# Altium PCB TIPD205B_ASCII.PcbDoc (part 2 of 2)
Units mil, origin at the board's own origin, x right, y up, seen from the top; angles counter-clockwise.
Board outline 684.25 x 4724.41 mil, 4 copper layers (Top Layer, Signal Layer 1, Signal Layer 2, Bottom Layer), stack 61.6 mil thick; 36 components, 24 nets, 156 pads, 59 vias.
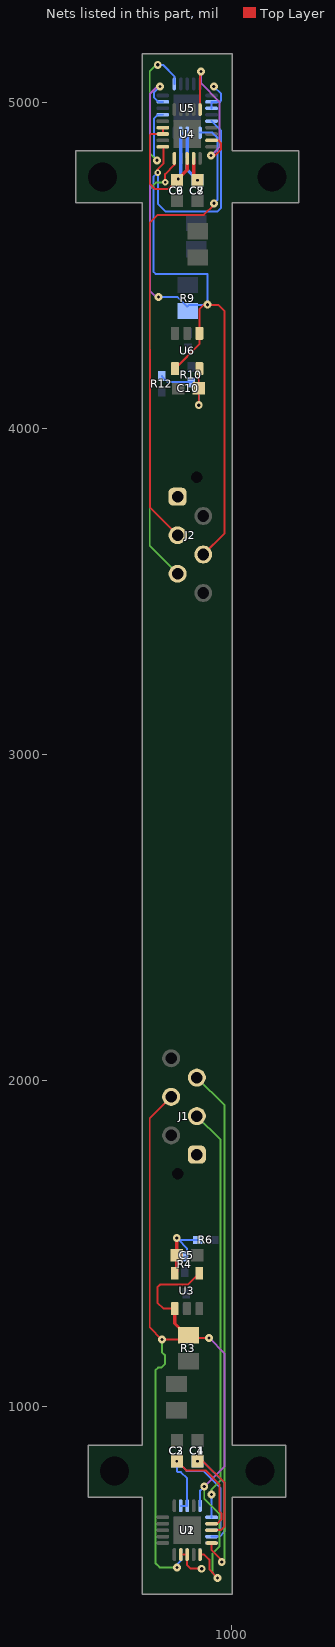
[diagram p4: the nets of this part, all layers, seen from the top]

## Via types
v1: diameter 24, hole 10, Top Layer to Bottom Layer, 24 vias
v2: diameter 20, hole 8, Top Layer to Bottom Layer, 19 vias
v3: diameter 24, hole 10, Top Layer to Bottom Layer, tented both sides, 12 vias
v4: diameter 20, hole 8, Top Layer to Bottom Layer, tented both sides, 4 vias

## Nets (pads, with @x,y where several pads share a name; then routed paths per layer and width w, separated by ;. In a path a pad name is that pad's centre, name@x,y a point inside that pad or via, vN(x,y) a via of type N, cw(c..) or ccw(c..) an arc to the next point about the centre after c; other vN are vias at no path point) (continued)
NetU4_12: U4.12 U4.16 | length 515.5
  Top Layer w6: U4.16@902.17,4977.76 902.17,5091.93 v3(905,5094.76) 906.35,5094.76 911.35,5089.76 v3@910.68,5089.09 ; v3(935.79,4836.95) 935.79,4838.18 942.2,4831.77 966.67,4856.24 966.67,4873.88 957.28,4883.27 U4.12@937.6,4883.27
  Signal Layer 1 w6: v3(905,5094.76) 905,5060.32 904.1,5059.42 961.22,5002.3 961.22,4862.38 v3(935.79,4836.95)
NetU5_12: U5.12 U5.16 | length 568.4
  Signal Layer 2 w6: v3(770,4822.17) 748,4844.17 748,5095.24 767.76,5115 v1@770,5115
  Bottom Layer w6: v3(770,4822.17) 760.43,4831.73 760.43,4936.66 760.39,4936.71 760.39,4947.89 760.43,4947.93 760.43,4950.2 772.24,4962.01 U5.12@787.99,4962.01 ; v1@770,5115 788.54,5115 823.43,5080.12 U5.16@823.43,5056.5
  other v1: 772.5,5115
VCM_H: J2.5 U4.6 | length 1364.8
  Top Layer w6: v4(795,4754.76) 795,4779.76 823.43,4808.19 U4.6@823.43,4828.15
  Signal Layer 1 w6: v4@794.26,4763.55 795,4762.8 v4(795,4754.76)
  Signal Layer 2 w6: v4(795,4754.76) 768.48,4754.76 748,4734.28 748,3639.8 J2.5@833.27,3554.53
VCM_V: J1.5 U1.6 | length 1596.2
  Top Layer w6: U1.6@937.6,582.48 937.6,560.79 968.59,529.79 v3(968.59,523.9)
  Signal Layer 2 w6: J1.5@892.32,2009.65 977.59,1924.38 977.59,532.9 v3(968.59,523.9)
VDD_H: C6.1 C7.2 C8.1 C9.2 C10.1 J2.1 R10.2 R12.2 U4.2 U4.3 U4.8 U4.9 U5.2 U5.3 U5.8 U5.9 U6.5 | length 1163.7
  Top Layer w6: U4.2@787.99,4922.64 U4.3@787.99,4902.95 751.94,4902.95 748,4899.02 748,4749.76 764,4733.76 803.84,4733.76 C6.1@831.3,4761.22 ; C7.2@882.48,4773.01 v2(894.29,4761.2) ; v1(898.23,4071.54) C10.1@898.23,4123.43 898.23,4181.5 U6.5@900.2,4183.46
  Top Layer w10: v2(835.04,4764.96) 862.8,4792.72 U4.8@862.8,4828.15 ; C7.2@882.48,4773.01 U4.9@882.48,4828.15
  Bottom Layer w6: R12.2@785,4160.79 802.68,4143.11 877.65,4143.11 898.23,4122.54 v1(898.23,4071.54) ; C9.2@831.3,4761.22 C9.2@843.11,4773.03 ; U5.8@862.58,4906.67 U5.8@862.8,4906.89 ; U5.3@937.6,4981.69 U5.2@937.6,5001.38 962.88,5001.42 966.38,5004.92 966.38,5010.47 966.67,5010.76 966.67,5026.1 944.49,5048.28 v3(944.49,5048.62)
  Bottom Layer w10: C9.2@843.11,4773.03 U5.9@843.11,4906.89 ; U5.8@862.8,4906.89 862.8,4792.7 v2(894.29,4761.2)
VDD_V: C1.1 C2.2 C3.1 C4.2 C5.1 J1.1 R4.2 R6.2 U1.2 U1.3 U1.8 U1.9 U2.2 U2.3 U2.8 U2.9 U3.5 | length 1734.8
  Top Layer w6: U3.5@818.74,1415.35 U3.5@824.65,1409.45 U3.5@830.55,1415.35 ; v2(831.3,833.43) 859.79,804.94 918.84,804.94 961.22,762.56 961.22,679.77 967.28,673.71 967.28,654.8 961.22,648.73 961.22,648.07 954.69,641.54 U1.9@937.6,641.54 ; U1.2@843.11,547.05 U1.3@862.8,547.05 862.8,514.53 873.58,503.74 v1(907.05,503.74) ; v2(894.29,833.43) 911.02,833.43 977.59,766.86 977.59,633.34 966.1,621.85 U1.8@938.54,621.85
  Top Layer w10: U3.5@830.55,1415.35 v1(830.55,1517.76)
  Bottom Layer w6: v1(830.55,1517.76) v1@836.42,1511.89 ; U2.2@843.11,696.65 U2.3@862.8,696.65 862.8,780.35 843.24,799.9 833.33,799.9 831.3,801.93 v2(831.3,833.43) 860.83,803.9 912.01,803.9 965.16,750.75 965.16,666.88 965.2,666.83 965.2,635.97 965.16,635.92 965.16,628.7 958.31,621.85 U2.8@937.6,621.85 ; R4.2@862.05,1470.51 862.05,1486.26 v1@836.42,1511.89 ; v2(894.29,833.43) 911.02,833.43 976.97,767.48 976.97,616.89 962.24,602.17 U2.9@937.6,602.17 ; R6.2@895.63,1511.89 v1@836.42,1511.89
VOUT_H: J2.3 U5.6 | length 1482.9
  Top Layer w6: J2.3@833.27,3672.64 748,3757.9 748,3857.51 748,4630.68 772.28,4654.96 914.01,4654.96 945,4685.94 v1(945,4690.35)
  Bottom Layer w6: U5.6@902.17,4906.89 939.88,4906.93 955.69,4891.12 955.69,4701.05 v1(945,4690.35)
VOUT_V: J1.3 U2.6 | length 1271.8
  Signal Layer 2 w6: J1.3@892.32,1891.54 965,1818.86 965,774.21 937.6,746.81 v1(937.6,731.06)
  Bottom Layer w6: U2.6@937.6,661.22 v1(937.6,731.06)
VREF_H: J2.4 R9.1 U4.5 U5.5 U5.14 U6.1 U6.4 | length 3231.5
  Top Layer w6: v2(772.24,4784.84) 772.24,4794.36 789.9,4812.01 789.9,4861.67 U4.5@787.99,4863.58 ; U6.4@825.39,4183.46 900.2,4258.27 U6.1@900.2,4291.73 900.2,4365.55 913.98,4379.33 957.28,4379.33 977.59,4359.02 977.59,3679.17 J2.4@912.01,3613.58
  Signal Layer 1 w6: v1@768.31,4402.95 748.62,4422.64 748.62,5025.62 771.62,5048.62 v3(779.13,5048.62)
  Bottom Layer w6: v1@772.24,4402.95 833.27,4402.95 862.8,4373.43 868.7,4379.33 v3@925,4379.33 ; v3(779.13,5048.62) 760.39,5029.87 760.39,5015.5 774.51,5001.38 U5.14@787.99,5001.38 ; v3(925,4379.76) 925,4473.84 766.16,4473.84 758.9,4481.1 758.9,4771.5 v2(772.24,4784.84) 773.07,4784.02 773.07,4688.94 797.01,4665 955.24,4665 966.59,4676.35 966.59,4913.33 U5.5@937.6,4942.32
  other v1: 775,4402.95
VREF_V: J1.4 R3.1 U1.5 U2.5 U2.14 U3.1 U3.4 | length 3107.9
  Top Layer w6: J1.4@813.58,1950.59 748,1885.01 748,1243.5 v1(785.29,1206.2) 859.59,1206.2 866.73,1213.35 868.7,1211.38 v1(929.72,1211.38) ; 824.65,1255.43 825.39,1254.69 ; U3.1@824.65,1301.18 790.2,1301.18 771.5,1319.88 771.5,1367.13 779.37,1375 865,1375 U3.4@899.45,1409.45 ; v1(831.3,507.68) v1@839.17,507.68 ; U1.5@903.11,547.05 914.92,547.05 930.67,531.3 930.67,501.33 v1@957,475
  Top Layer w9.84: 824.65,1276.57 U3.1@824.65,1301.18
  Top Layer w10: 824.65,1255.43 824.65,1276.57 ; 825.39,1254.69 R3.1@866.73,1213.35
  Signal Layer 1 w6: v1(915,755.71) 977.59,818.3 977.59,1163.51 v1(929.72,1211.38)
  Signal Layer 2 w6: v1(785.29,1206.2) 785.29,1167.07 794.9,1157.46 794.9,1131.76 783.24,1120.1 773.55,1120.1 765,1111.55 765,521.2 778.53,507.68 v1(831.3,507.68) ; v1(915,755.71) 915,718.74 961.22,672.52 961.22,571.22 940,550 940,492 v1@957,475
  Bottom Layer w6: v1(831.3,507.68) 831.3,516.24 843.11,528.05 U2.14@843.11,547.05 ; U2.5@902.17,696.65 902.17,742.87 v1(915,755.71)
  other v1: 956,475
pads on no net: J1.MH J2.MH U1.4 U1.11 U2.4 U2.11 U4.4 U4.11 U5.4 U5.11
copper on no net: | length 440
  Top Layer w6: -460,7990 -20,7990

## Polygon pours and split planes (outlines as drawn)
VDD_H on Signal Layer 2 "VDD_H_L03_P009" (solid, remove dead copper, pour order 9): 732.87,5141.54 992.72,5141.54 992.72,3715 732.87,3715
VDD_V on Signal Layer 2 "VDD_V_L03_P010" (solid, remove dead copper, pour order 10): 732.87,1865 988.78,1865 988.78,436.81 732.87,436.81
GND_V on Signal Layer 1 "GND_V_L02_P008" (solid, remove dead copper, pour order 8): 732.87,1865 988.78,1865 988.78,436.81 732.87,436.81
GND_H on Signal Layer 1 "GND_H_L02_P007" (solid, remove dead copper, pour order 7): 732.87,5141.54 992.72,5141.54 992.72,3715 732.87,3715

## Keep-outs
Keep-Out Layer:
  lines w10: 515.67,4691.54 ccw(c520.67,4691.54) 520.67,4686.53 ; 515.67,4691.54 ccw(c520.67,4691.54) 520.67,4686.53 ; 515.67,4691.54 ccw(c520.67,4691.54) 520.67,4686.53 ; 515.67,4691.54 ccw(c520.67,4691.54) 520.67,4686.53 ; 515.67,4691.54 515.67,4851.38 ; 515.67,4691.54 515.67,4851.38 ; 515.67,4851.38 cw(c520.67,4851.38) 520.67,4856.38 ; 515.67,4851.38 cw(c520.67,4851.38) 520.67,4856.38 ; 515.67,4851.38 cw(c520.67,4851.38) 520.67,4856.38 ; 515.67,4851.38 cw(c520.67,4851.38) 520.67,4856.38 ; 520.67,4686.53 720,4686.53 ; 520.67,4686.53 720,4686.53 ; 520.67,4856.38 720,4856.38 ; 520.67,4856.38 720,4856.38 ; 555.04,723.03 ccw(c560.04,723.03) 560.04,718.03 ; 555.04,723.03 ccw(c560.04,723.03) 560.04,718.03 ; 555.04,723.03 ccw(c560.04,723.03) 560.04,718.03 ; 555.04,723.03 ccw(c560.04,723.03) 560.04,718.03 ; 555.04,723.03 ccw(c560.04,723.03) 560.04,718.03 ; 555.04,723.03 ccw(c560.04,723.03) 560.04,718.03 ; 555.04,723.03 555.04,882.87 ; 555.04,723.03 555.04,882.87 ; 555.04,723.03 555.04,882.87 ; 555.04,882.87 cw(c560.04,882.87) 560.04,887.88 ; 555.04,882.87 cw(c560.04,882.87) 560.04,887.88 ; 555.04,882.87 cw(c560.04,882.87) 560.04,887.88 ; 555.04,882.87 cw(c560.04,882.87) 560.04,887.88 ; 555.04,882.87 cw(c560.04,882.87) 560.04,887.88 ; 555.04,882.87 cw(c560.04,882.87) 560.04,887.88 ; 560.04,718.03 720,718.03 ; 560.04,718.03 720,718.03 ; 560.04,718.03 720,718.03 ; 560.04,887.88 720,887.88 ; 560.04,887.88 720,887.88 ; 560.04,887.88 720,887.88 ; 720,425 ccw(c725,425) 725,420 ; 720,425 ccw(c725,425) 725,420 ; 720,425 ccw(c725,425) 725,420 ; 720,425 ccw(c725,425) 725,420 ; 720,425 ccw(c725,425) 725,420 ; 720,425 ccw(c725,425) 725,420 ; 720,425 ccw(c725,425) 725,420 ; 720,425 ccw(c725,425) 725,420 ; 720,425 720,718.03 ; 720,425 720,718.03 ; 720,425 720,718.03 ; 720,887.88 720,4686.53 ; 720,887.88 720,4686.53 ; 720,4856.38 720,5149.41 ; 720,4856.38 720,5149.41 ; 720,5149.41 cw(c725,5149.41) 725,5154.41 ; 720,5149.41 cw(c725,5149.41) 725,5154.41 ; 720,5149.41 cw(c725,5149.41) 725,5154.41 ; 720,5149.41 cw(c725,5149.41) 725,5154.41 ; 720,5149.41 cw(c725,5149.41) 725,5154.41 ; 720,5149.41 cw(c725,5149.41) 725,5154.41 ; 720,5149.41 cw(c725,5149.41) 725,5154.41 ; 720,5149.41 cw(c725,5149.41) 725,5154.41 ; 725,420 1000.59,420 ; 725,420 1000.59,420 ; 725,420 1000.59,420 ; 725,420 1000.59,420 ; 725,5154.41 1000.59,5154.41 ; 725,5154.41 1000.59,5154.41 ; 725,5154.41 1000.59,5154.41 ; 725,5154.41 1000.59,5154.41 ; 1000.59,420 ccw(c1000.59,425) 1005.59,425 ; 1000.59,420 ccw(c1000.59,425) 1005.59,425 ; 1000.59,420 ccw(c1000.59,425) 1005.59,425 ; 1000.59,420 ccw(c1000.59,425) 1005.59,425 ; 1000.59,420 ccw(c1000.59,425) 1005.59,425 ; 1000.59,420 ccw(c1000.59,425) 1005.59,425 ; 1000.59,420 ccw(c1000.59,425) 1005.59,425 ; 1000.59,420 ccw(c1000.59,425) 1005.59,425 ; 1000.59,5154.41 cw(c1000.59,5149.41) 1005.59,5149.41 ; 1000.59,5154.41 cw(c1000.59,5149.41) 1005.59,5149.41 ; 1000.59,5154.41 cw(c1000.59,5149.41) 1005.59,5149.41 ; 1000.59,5154.41 cw(c1000.59,5149.41) 1005.59,5149.41 ; 1000.59,5154.41 cw(c1000.59,5149.41) 1005.59,5149.41 ; 1000.59,5154.41 cw(c1000.59,5149.41) 1005.59,5149.41 ; 1000.59,5154.41 cw(c1000.59,5149.41) 1005.59,5149.41 ; 1000.59,5154.41 cw(c1000.59,5149.41) 1005.59,5149.41 ; 1005.59,425 1005.59,718.03 ; 1005.59,425 1005.59,718.03 ; 1005.59,718.03 1165.55,718.03 ; 1005.59,718.03 1165.55,718.03 ; 1005.59,887.88 1165.55,887.88 ; 1005.59,887.88 1005.59,4686.53 ; 1005.59,887.88 1005.59,4686.53 ; 1005.59,887.88 1165.55,887.88 ; 1005.59,4686.53 1204.92,4686.53 ; 1005.59,4686.53 1204.92,4686.53 ; 1005.59,4856.38 1204.92,4856.38 ; 1005.59,4856.38 1005.59,5149.41 ; 1005.59,4856.38 1005.59,5149.41 ; 1005.59,4856.38 1204.92,4856.38 ; 1165.55,718.03 ccw(c1165.55,723.03) 1170.55,723.03 ; 1165.55,718.03 ccw(c1165.55,723.03) 1170.55,723.03 ; 1165.55,718.03 ccw(c1165.55,723.03) 1170.55,723.03 ; 1165.55,718.03 ccw(c1165.55,723.03) 1170.55,723.03 ; 1165.55,887.88 cw(c1165.55,882.87) 1170.55,882.87 ; 1165.55,887.88 cw(c1165.55,882.87) 1170.55,882.87 ; 1165.55,887.88 cw(c1165.55,882.87) 1170.55,882.87 ; 1165.55,887.88 cw(c1165.55,882.87) 1170.55,882.87 ; 1170.55,723.03 1170.55,882.87 ; 1170.55,723.03 1170.55,882.87 ; 1204.92,4686.53 ccw(c1204.92,4691.54) 1209.92,4691.54 ; 1204.92,4686.53 ccw(c1204.92,4691.54) 1209.92,4691.54 ; 1204.92,4686.53 ccw(c1204.92,4691.54) 1209.92,4691.54 ; 1204.92,4686.53 ccw(c1204.92,4691.54) 1209.92,4691.54 ; 1204.92,4856.38 cw(c1204.92,4851.38) 1209.92,4851.38 ; 1204.92,4856.38 cw(c1204.92,4851.38) 1209.92,4851.38 ; 1204.92,4856.38 cw(c1204.92,4851.38) 1209.92,4851.38 ; 1204.92,4856.38 cw(c1204.92,4851.38) 1209.92,4851.38 ; 1209.92,4691.54 1209.92,4851.38 ; 1209.92,4691.54 1209.92,4851.38
  text ".Layer_Name" at 577,-858.49 h60

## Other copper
Top Layer:
  text ".Layer_Name" at 577,-858.49 h60
Bottom Layer:
  text ".Layer_Name" at 577,-858.49 h60

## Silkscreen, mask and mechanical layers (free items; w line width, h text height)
Top Overlay:
  lines w6: 902.17,5025.93 912.17,5035.93 902.17,5045.93
  lines w7.09: 817.17,5035.93 912.17,5035.93
  lines w10: 725,621.85 752.56,621.85 ; 725,4954.13 760.43,4954.13 ; 965.16,4954.13 1000.59,4954.13 ; 973.03,621.85 1000.59,621.85
  text ".EVM_Orderable" at 975,2355 h50 r90
  text ".Layer_Name" at 577,-858.49 h60
Bottom Overlay:
  lines w10: 725,621.85 752.56,621.85 ; 725,4954.13 760.43,4954.13 ; 965.16,4954.13 1000.59,4954.13 ; 973.03,621.85 1000.59,621.85
  text ".PCB_Rev" at 915,3020 h50 r270
  text ".PRJ_Number" at 915,2675 h50 r270
  text ".Layer_Name" at 577,-858.49 h60
Top Paste:
  text ".Layer_Name" at 577,-858.49 h60
Bottom Paste:
  text ".Layer_Name" at 577,-858.49 h60
Top Solder:
  lines w10: 823.43,4960.43 823.43,4987.99 ; 831.3,4771.46 834.25,4774.41 839.17,4774.41
  text ".Layer_Name" at 577,-858.49 h60
  text ".Layer_Name" at 577,-858.49 h60
Bottom Solder:
  lines w10: 823.43,4944.69 831.3,4952.56 ; 882.48,4917.17 882.48,4917.17
  text ".Layer_Name" at 577,-858.49 h60
Drill Guide:
  text ".Layer_Name" at 577,-858.49 h60
M1 Board Outline:
  lines w10: 725,2295.08 1000.59,2295.08 ; 730,3279.33 1005.59,3279.33 1119.76,3279.33 1170.94,3330.51 ; 1005.59,2295.08 1119.76,2295.08 1170.94,2346.26 ; 520.67,4691.54 725,4691.54 725,882.87 560.04,882.87 560.04,723.03 725,723.03 725,425 1000.59,425 1000.59,723.03 1165.55,723.03 1165.55,882.87 1000.59,882.87 1000.59,4691.54 1204.92,4691.54 1204.92,4851.38 1000.59,4851.38 1000.59,5149.41 725,5149.41 725,4851.38 520.67,4851.38 520.67,4691.54
  text "score line" at 1180,3327.95 h20
  text "score line" at 1175,2360 h20
  text ".Layer_Name" at 577,-858.49 h60
M2 Board Dimensions:
  rectangle: 125,-400 500,-275
  rectangle: 0,-275 125,-150
  lines w7: 0,-275 1000,-275 ; 125,-400 125,-150 ; 250,-400 250,-150 ; 500,-400 500,-150 ; 750,-400 750,-150 ; 0,-400 0,-150 1000,-150 1000,-400 0,-400
  text ".Layer_Name" at 577,-858.49 h60
M3 3D STEP Top:
  text ".Layer_Name" at 577,-858.49 h60
M4 3D STEP Bottom:
  text ".Layer_Name" at 577,-858.49 h60
M5 Assembly Top:
  lines w10: -292,-930.17 6308,-930.17 ; -292,-726.83 6310,-726.83 ; -292,-523.5 -292,-1133.5 3713,-1133.5 6310,-1133.5 6310,-523.5 -291.5,-523.5 -291.5,-1133.5 1284,-1133.5 ; 2173,-1133.5 2173,-523.5 ; 3440,-726.83 3440,-523.5 ; 4280,-726.83 4280,-523.5 ; 4902,-1140 4902,-937.17
  text "COMPONENTS MARKED 'DNP' SHOULD NOT BE POPULATED." at 1153.5,-318.5 h60
  text "ASSEMBLY VARIANT:" at 1153,-434 h60
  text ".VariantName" at 2189,-434 h60
  text "PCB VIEWED FROM TOP SIDE" at -228.5,-655.67 h60
  text "BOARD #:" at 2248,-655.67 h60
  text ".PRJ_Number" at 2793.5,-655.67 h60
  text "REV:" at 3638,-655.67 h60
  text ".PCB_Rev" at 3929.5,-655.67 h60
  text "SVN REV:" at 4476,-655.67 h60
  text ".VersionControl_RevNumber" at 4982,-655.67 h60
  text "TID #:" at 2248,-859 h60
  text ".TID" at 2793.5,-859 h60
  text "PLOT NAME =" at -228.5,-1064.34 h60
  text ".plot_File_Name" at 577,-1064.34 h60
  text "GENERATED    :" at 2250,-1064.34 h60
  text ".Print_Date" at 3119.5,-1064.34 h60
  text ".Print_Time" at 3848.5,-1064.34 h60
  text "TEXAS INSTRUMENTS" at 5113,-1064.34 h60
M6 Assembly Bottom:
  lines w10: -292.5,-727.33 6309.5,-727.33 ; -290.5,-930.67 6309.5,-930.67 ; 1115.5,-1140.5 1115.5,-937.67 ; 1737.5,-727.33 1737.5,-524 ; 2577.5,-727.33 2577.5,-524 ; 3844.5,-1134 3844.5,-524 ; 4733.5,-1134 6309,-1134 6309,-524 -292.5,-524 -292.5,-1134 2304.5,-1134 6309.5,-1134 6309.5,-524
  text "COMPONENTS MARKED 'DNP' SHOULD NOT BE POPULATED." at 6102,-318 h60
  text ".VariantName" at 5058,-434 h60
  text "ASSEMBLY VARIANT:" at 6097,-434 h60
  text ".VersionControl_RevNumber" at 1035.5,-656.17 h60
  text "SVN REV:" at 1541.5,-656.17 h60
  text ".PCB_Rev" at 2088,-656.17 h60
  text "REV:" at 2379.5,-656.17 h60
  text ".PRJ_Number" at 3224,-656.17 h60
  text "BOARD #:" at 3769.5,-656.17 h60
  text "PCB VIEWED FROM BOTTOM SIDE" at 6246,-656.17 h60
  text ".TID" at 3224,-859.5 h60
  text "TID #:" at 3769.5,-859.5 h60
  text "TEXAS INSTRUMENTS" at 904.5,-1064.84 h60
  text ".Print_Time" at 2169,-1064.84 h60
  text ".Print_Date" at 2898,-1064.84 h60
  text "GENERATED    :" at 3767.5,-1064.84 h60
  text ".plot_File_Name" at 5440.5,-1064.84 h60
  text "PLOT NAME =" at 6246,-1064.84 h60
M9 Title Sheet:
  lines w10: -491.5,1041.5 -291.5,1041.5 ; -491.5,3416.5 -291.5,3416.5 ; -491.5,5791.5 -291.5,5791.5 ; 2008.5,-1333.5 2008.5,-1133.5 ; 2008.5,7966.5 2008.5,8166.5 ; 4508.5,-1333.5 4508.5,-1133.5 ; 4508.5,7966.5 4508.5,8166.5 ; 6321,-1133.5 6321,-523.5 11303.5,-523.5 ; 7008.5,-1333.5 7008.5,-1133.5 ; 7008.5,7966.5 7008.5,8166.5 ; 9508.5,-1333.5 9508.5,-1133.5 ; 9508.5,7966.5 9508.5,8166.5 ; 11303.5,-1133.5 11303.5,-523.5 ; 11303.5,-823.5 14303.5,-823.5 ; 11303.5,-223.5 14303.5,-223.5 ; 11304.5,370.5 14304.5,370.5 ; 12008.5,-1333.5 12008.5,-1133.5 ; 12008.5,7966.5 12008.5,8166.5 ; 12808.5,-1123.5 12808.5,-523.5 ; 14303.5,-523.5 11303.5,-523.5 ; 14303.5,76.5 11303.5,76.5 ; 14308.5,66.5 14308.5,-1133.5 ; 14308.5,871 11304.5,871 11303.5,871 11303.5,370.5 11303.5,76.5 ; 14308.5,1041.5 14508.5,1041.5 ; 14308.5,3416.5 14508.5,3416.5 ; 14308.5,5791.5 14508.5,5791.5 ; 11303.5,-523.5 11303.5,76.5 ; 14308.5,-1133.5 -291.5,-1133.5 -291.5,7966.5 14308.5,7966.5 14308.5,-1133.5 ; -491.5,-1333.5 14508.5,-1333.5 14508.5,8166.5 -491.5,8166.5 -491.5,-1333.5
  text "1" at 739.84,8036.5 h70
  text "2" at 3235.5,8036.5 h70
  text "3" at 5724.84,8036.5 h70
  text "4" at 8231.51,8036.5 h70
  text "5" at 10730.5,8036.5 h70
  text "6" at 13235.5,8036.5 h70
  text "A" at -416.5,6893.5 h70
  text "A" at 14383.5,6893.5 h70
  text "B" at -416.5,4513.5 h70
  text "B" at 14383.5,4513.5 h70
  text "C" at -416.5,2138.5 h70
  text "C" at 14383.5,2138.5 h70
  text "PROJECT TITLE:" at 11343.5,277.5 h45
  text ".PRJ_Title" at 11393.5,144.17 h70
  text "DESIGNED FOR:" at 11343.5,-23.5 h45
  text ".PRJ_Customer" at 11393.5,-163.5 h70
  text "D" at -416.5,-231.5 h70
  text "D" at 14383.5,-231.5 h70
  text "FILE NAME:" at 11343.5,-323.5 h45
  text ".PCB_File_Name_No_Path" at 11393.5,-443.5 h70
  text "Texas Instruments (TI) and/or its licensors do not warrant the accuracy or completeness of this specification" at 6374,-605.34 h45
  text "ENGINEER:" at 11343.5,-613.5 h45
  text "LAYOUT BY:" at 12848.5,-613.5 h45
  text "or any information contained therein. TI and/or its licensors do not warrant that this design will meet" at 6329.01,-718 h45
  text ".PRJ_Engineer" at 11393.5,-768.49 h70
  text ".PCB_Layout" at 12899,-768.49 h70
  text "the specifications, will be suitable for your application or fit for any particular purpose, or will operate in" at 6329.01,-830.67 h45
  text ".Layer_Name" at 577,-858.49 h60
  text "ALTIUM DESIGNER VERSION:" at 12848.5,-923.5 h45
  text "an implementation. TI and/or its licensors do not warrant that the design is production worthy. You should" at 6329.01,-943.33 h45
  text "completely validate and test your design implementation to confirm the system functionality for your application." at 6374,-1056 h45
  text ".print_Scale" at 11393.5,-1056.83 h70
  text ".Application_BuildNumber" at 12899,-1056.83 h70
  text "1" at 739.84,-1263.5 h70
  text "2" at 3235.5,-1263.5 h70
  text "3" at 5724.84,-1263.5 h70
  text "4" at 8231.51,-1263.5 h70
  text "5" at 10730.5,-1263.5 h70
  text "6" at 13235.5,-1263.5 h70
M10 Fab Notes:
  drawing of 189 lines, arcs and shapes, not listed
  text "DESIGN INFORMATION" at 12381.02,6028 h60
  text "MIN. TRACK WIDTH:" at 11736.46,5848 h60
  text "6" at 12832.7,5848 h60
  text "MIL" at 12987.46,5848 h60
  text "MIN. CLEARANCE:" at 11736.46,5716 h60
  text "0.2" at 12772.7,5716 h60
  text "mm" at 12987.46,5716 h60
  text "MIN. VIA PAD SIZE:" at 11736.46,5584 h60
  text "24" at 12802.71,5584 h60
  text "MIL" at 12987.46,5584 h60
  text "0.05mm (2MIL)" at 12431.46,5442.29 h60
  text "MINIMUM ANNULAR RING" at 11407.23,5438 h60
  text "EXTERNAL" at 13139.46,5438 h60
  text "PER" at 11607.23,5320 h60
  text "IPC-D-275 CLASS 2 LEVEL C" at 11827.23,5320 h60
  text "MIL, HOLES" at 13315.46,5207.71 h60
  text "+/-" at 12923,5207 h60
  text "+/-" at 13777,5207 h60
  text "REGISTRATION TOLERANCES:" at 11407.23,5202 h60
  text "METAL" at 12607,5202 h60
  text "5" at 13183.2,5202 h60
  text "3" at 14016.2,5202 h60
  text "MIL" at 14132.46,5202 h60
  text "+/-" at 13777,5089 h60
  text "HOLE SIZE TOLERANCE (UNLESS OTHERWISE SPECIFIED):" at 11407.23,5084 h60
  text "3" at 14016.2,5084 h60
  text "MIL" at 14132.46,5084 h60
  text "MATERIAL:" at 11332.46,4874.54 h60
  text "FR-4 High Tg" at 12318.9,4734.21 h60
  text "FR-408" at 11753.46,4725.64 h60
  text "OTHER" at 13241.46,4725.64 h60
  text "X" at 12164,4722 h60
  text "62 MIL (1.6mm) +/-10%" at 12073.56,4562.92 h60
  text "X" at 11930,4560 h60
  text "THICKNESS:" at 11407.23,4558.64 h60
  text "TOLERANCE:" at 11407.23,4400.64 h60
  text "X" at 12246.53,4400.64 h60
  text "ANSI IPC-6012 TYPE 3 CLASS 2" at 12433.48,4400.64 h60
  text "OTHER +/-" at 12433.46,4244.64 h60
  text "BOW & TWIST:" at 11407.23,4087.64 h60
  text "X" at 12246.53,4087.64 h60
  text "ANSI IPC-6012 TYPE 3 CLASS 2" at 12433.48,4087.64 h60
  text "OTHER +/-" at 12433.46,3929.13 h60
  text "DRILLING:" at 11332.46,3790.64 h60
  text "REFERENCE:" at 11407.23,3673.64 h60
  text "X" at 12055.46,3673.64 h60
  text "AS SHOWN" at 12242.46,3673.64 h60
  text "X" at 12956.46,3673.64 h60
  text "NC_DRILL FILES" at 13093.46,3673.64 h60
  text "PTH MIN COPPER THICKNESS:" at 11407.23,3515.64 h60
  text "X" at 12757.46,3515.64 h60
  text "1MIL" at 12894.46,3515.64 h60
  text "OTHER" at 13391.46,3515.64 h60
  text "BOARD FINISH:" at 11332.46,3356.64 h60
  text "SILKSCREEN:" at 11487.68,3238.64 h60
  text "X" at 12436.46,3238.64 h60
  text "TOP" at 12562.46,3238.64 h60
  text "X" at 12946.46,3238.64 h60
  text "BOTTOM" at 13073.46,3238.64 h60
  text "SILKSCREEN COLOR:" at 11487.68,3071.64 h60
  text "X" at 12435.42,3071.64 h60
  text "WHITE" at 12562.46,3071.64 h60
  text "OTHER" at 13073.46,3071.64 h60
  text "X" at 12566.42,2912.44 h60
  text "GREEN" at 12693.46,2912.44 h60
  text "OTHER" at 13311.46,2912.44 h60
  text "SOLDER RESIST COLOR:" at 11487.68,2901.64 h60
  text "X" at 12566.42,2742.44 h60
  text "MATTE" at 12693.46,2742.44 h60
  text "SEMI-GLOSS" at 13311,2741.8 h60
  text "IMMERSION GOLD (ENIG)" at 12393.46,2553.92 h60
  text "ENEPIG" at 13731,2550.64 h60
  text "SURFACE FINISH:" at 11332.46,2549.64 h60
  text "X" at 12206.51,2549.64 h60
  text "IMM. TIN/SILVER OR EQUIV" at 11662,2392.64 h60
  text "OTHER" at 13093.46,2392.64 h60
  text "ARRAY/PANEL:" at 11332.46,2213.64 h60
  text "CUT AND TRIM PER M1 BOARD OUTLINE" at 12393.46,2209.35 h60
  text "N.C. ROUTE" at 12393.46,2057.64 h60
  text "X" at 13072.46,2057.64 h60
  text "V. SCORE" at 13259.46,2057.64 h60
  text "CERTIFICATION:" at 11332.46,1920.64 h60
  text "MATERIALS AND WORKMANSHIP FOR ALL PCBS" at 12057.46,1920.64 h60
  text "TO MEET OR EXCEED THE REQUIREMENTS OF:" at 12057.46,1822.64 h60
  text "X" at 11683.96,1686.13 h60
  text "ANSI IPC-A-600F CLASS ->" at 11822.96,1686.13 h60
  text "X" at 13462.02,1686.13 h60
  text "2" at 13580.96,1686.14 h60
  text "1" at 13265.96,1684.64 h60
  text "3" at 13934.96,1684.64 h60
  text "X" at 11686.02,1526.64 h60
  text "UL 94V-0" at 11822.96,1526.64 h60
  text "X" at 12498.02,1526.64 h60
  text "RoHS" at 12634.96,1526.64 h60
  text "OTHER" at 13279.36,1526.64 h60
  text "PER ORDER" at 13676.42,1526.64 h60
  text "ADDITIONAL REQUIREMENTS:" at 11332.46,1385.64 h60
  text "MICROSECTION:" at 11407.23,1270.64 h60
  text "YES" at 12312.96,1270.64 h60
  text "REQUIRED" at 13174.46,1114.49 h60
  text "BARE BOARD ELEC. TEST:" at 11407.23,1111.64 h60
  text "NONE" at 12712.96,1111.64 h60
  text "X" at 13047.46,1111.64 h60
  text "PER ORDER" at 13766.46,1111.64 h60
  text "MANUFACTURER'S UL:" at 11407.23,954.64 h60
  text "RAIL" at 12572.96,950.35 h60
  text "METAL" at 13064.77,950.35 h60
  text "X" at 13440,950 h60
  text "SILK" at 13576.46,950.35 h60
  text ".Layer_Name" at 577,-858.49 h60
M11 Gerber Information:
  lines w10: -292,-930.17 6308,-930.17 ; -292,-726.83 6310,-726.83 ; -292,-523.5 -292,-1133.5 3713,-1133.5 6310,-1133.5 6310,-523.5 -291.5,-523.5 -291.5,-1133.5 1284,-1133.5 ; 2173,-1133.5 2173,-523.5 ; 3440,-726.83 3440,-523.5 ; 4280,-726.83 4280,-523.5 ; 4902,-1140 4902,-937.17
  text "ALL ARTWORK VIEWED FROM TOP SIDE" at -228.5,-655.67 h60
  text "BOARD #:" at 2248,-655.67 h60
  text ".PRJ_Number" at 2793.5,-655.67 h60
  text "REV:" at 3638,-655.67 h60
  text ".PCB_Rev" at 3929.5,-655.67 h60
  text "SVN REV:" at 4476,-655.67 h60
  text ".VersionControl_RevNumber" at 4982,-655.67 h60
  text "LAYER NAME =" at -228.5,-858.49 h60
  text "TID #:" at 2248,-859 h60
  text ".TID" at 2793.5,-859 h60
  text "PLOT NAME =" at -228.5,-1064.34 h60
  text ".plot_File_Name" at 577,-1064.34 h60
  text "GENERATED    :" at 2250,-1064.34 h60
  text ".Print_Date" at 3119.5,-1064.34 h60
  text ".Print_Time" at 3848.5,-1064.34 h60
  text "TEXAS INSTRUMENTS" at 5113,-1064.34 h60
M12 Stackup:
  drawing of 295 lines, arcs and shapes, not listed
  text "Layer" at 9785.74,7685 h60
  text "Name" at 10195.66,7685 h60
  text "Material" at 11135.4,7685 h60
  text "Thickness" at 11995.16,7685 h60
  text "Constant" at 12645,7685 h60
  text "Board Layer Stack" at 13214.86,7685 h60
  text "1" at 9785.74,7565 h60
  text "Top Overlay" at 10195.66,7565 h60
  text "2" at 9785.74,7445 h60
  text "Top Solder" at 10195.66,7445 h60
  text "Solder Resist" at 11135.4,7445 h60
  text "0.40mil" at 11995.16,7445 h60
  text "3.5" at 12645,7445 h60
  text "3" at 9785.74,7325 h60
  text "Top Layer" at 10195.66,7325 h60
  text "Copper" at 11135.4,7325 h60
  text "1.40mil" at 11995.16,7325 h60
  text "4" at 9785.74,7205 h60
  text "Dielectric 1" at 10195.66,7205 h60
  text "FR-4" at 11135.4,7205 h60
  text "8.00mil" at 11995.16,7205 h60
  text "4.2" at 12645,7205 h60
  text "5" at 9785.74,7085 h60
  text "Signal Layer 1" at 10195.66,7085 h60
  text "Copper" at 11135.4,7085 h60
  text "1.40mil" at 11995.16,7085 h60
  text "6" at 9785.74,6965 h60
  text "Dielectric 2" at 10195.66,6965 h60
  text "FR-4" at 11135.4,6965 h60
  text "40.00mil" at 11995.16,6965 h60
  text "4.2" at 12645,6965 h60
  text "7" at 9785.74,6845 h60
  text "Signal Layer 2" at 10195.66,6845 h60
  text "Copper" at 11135.4,6845 h60
  text "1.40mil" at 11995.16,6845 h60
  text "8" at 9785.74,6725 h60
  text "Dielectric 3" at 10195.66,6725 h60
  text "FR-4" at 11135.4,6725 h60
  text "8.00mil" at 11995.16,6725 h60
  text "4.2" at 12645,6725 h60
  text "9" at 9785.74,6605 h60
  text "Bottom Layer" at 10195.66,6605 h60
  text "Copper" at 11135.4,6605 h60
  text "1.40mil" at 11995.16,6605 h60
  text "10" at 9785.74,6485 h60
  text "Bottom Solder" at 10195.66,6485 h60
  text "Solder Resist" at 11135.4,6485 h60
  text "0.40mil" at 11995.16,6485 h60
  text "3.5" at 12645,6485 h60
  text "11" at 9785.74,6365 h60
  text "Bottom Overlay" at 10195.66,6365 h60
  text ".Layer_Name" at 577,-858.49 h60
M13 Component Bodies Top:
  text ".Layer_Name" at 577,-858.49 h60
M14 Component Bodies Bottom:
  text ".Layer_Name" at 577,-858.49 h60
M15 Courtyards Top:
  text ".Layer_Name" at 577,-858.49 h60
M16 Courtyards Bottom:
  text ".Layer_Name" at 577,-858.49 h60
Drill Drawing:
  circle w10: c5683.72,3017.64 r27.63
  lines w10: 5656.09,2741.38 5656.09,2755.19 5669.9,2769 5656.09,2782.82 5656.09,2796.63 5669.9,2796.63 5683.72,2782.82 5697.53,2796.63 5711.34,2796.63 5711.34,2782.82 5697.53,2769 5711.34,2755.19 5711.34,2741.38 5697.53,2741.38 5683.72,2755.19 5669.9,2741.38 5656.09,2741.38 ; 5656.09,2920.95 5711.34,2920.95 5683.72,2865.7 5656.09,2920.95 ; 5656.09,3141.96 5683.72,3114.34 5711.34,3141.96 5683.72,3169.59 5656.09,3141.96 ; 5656.09,3252.47 5669.9,3252.47 5669.9,3238.66 5697.53,3238.66 5697.53,3252.47 5711.34,3252.47 5711.34,3280.1 5697.53,3280.1 5697.53,3293.91 5669.9,3293.91 5669.9,3280.1 5656.09,3280.1 5656.09,3252.47
  lines w12: 5606,2704.08 7584.02,2704.08 ; 5606,3325.68 7584.02,3325.68 ; 5943.86,2579.76 5943.86,3450 ; 6275.86,2579.76 6275.86,3450 ; 6912.43,2579.76 6912.43,3450 ; 7171.57,2579.76 7171.57,3450 ; 5606,2579.76 7584.02,2579.76 7584.02,3450 5606,3450 5606,2579.76
  text "Symbol" at 5680.59,3362.98 h72
  text "Quantity" at 5981.16,3362.98 h72
  text "Finished Hole Size" at 6313.16,3362.98 h72
  text "Plated" at 6949.72,3362.98 h72
  text "Hole Type" at 7208.86,3362.98 h72
  text "2" at 5981.16,3238.66 h60
  text "35.43mil (0.900mm)" at 6313.16,3238.66 h60
  text "NPTH" at 6949.72,3238.66 h60
  text "Round" at 7208.86,3238.66 h60
  text "4" at 5981.16,3114.34 h60
  text "88.98mil (2.260mm)" at 6313.16,3114.34 h60
  text "NPTH" at 6949.72,3114.34 h60
  text "Round" at 7208.86,3114.34 h60
  text "23" at 5981.16,2990.02 h60
  text "8.00mil (0.203mm)" at 6313.16,2990.02 h60
  text "PTH" at 6949.72,2990.02 h60
  text "Round" at 7208.86,2990.02 h60
  text "36" at 5981.16,2865.7 h60
  text "10.00mil (0.254mm)" at 6313.16,2865.7 h60
  text "PTH" at 6949.72,2865.7 h60
  text "Round" at 7208.86,2865.7 h60
  text "12" at 5981.16,2741.38 h60
  text "35.43mil (0.900mm)" at 6313.16,2741.38 h60
  text "PTH" at 6949.72,2741.38 h60
  text "Round" at 7208.86,2741.38 h60
  text "77 Total" at 5981.16,2617.06 h60
  text ".Layer_Name" at 577,-858.49 h60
